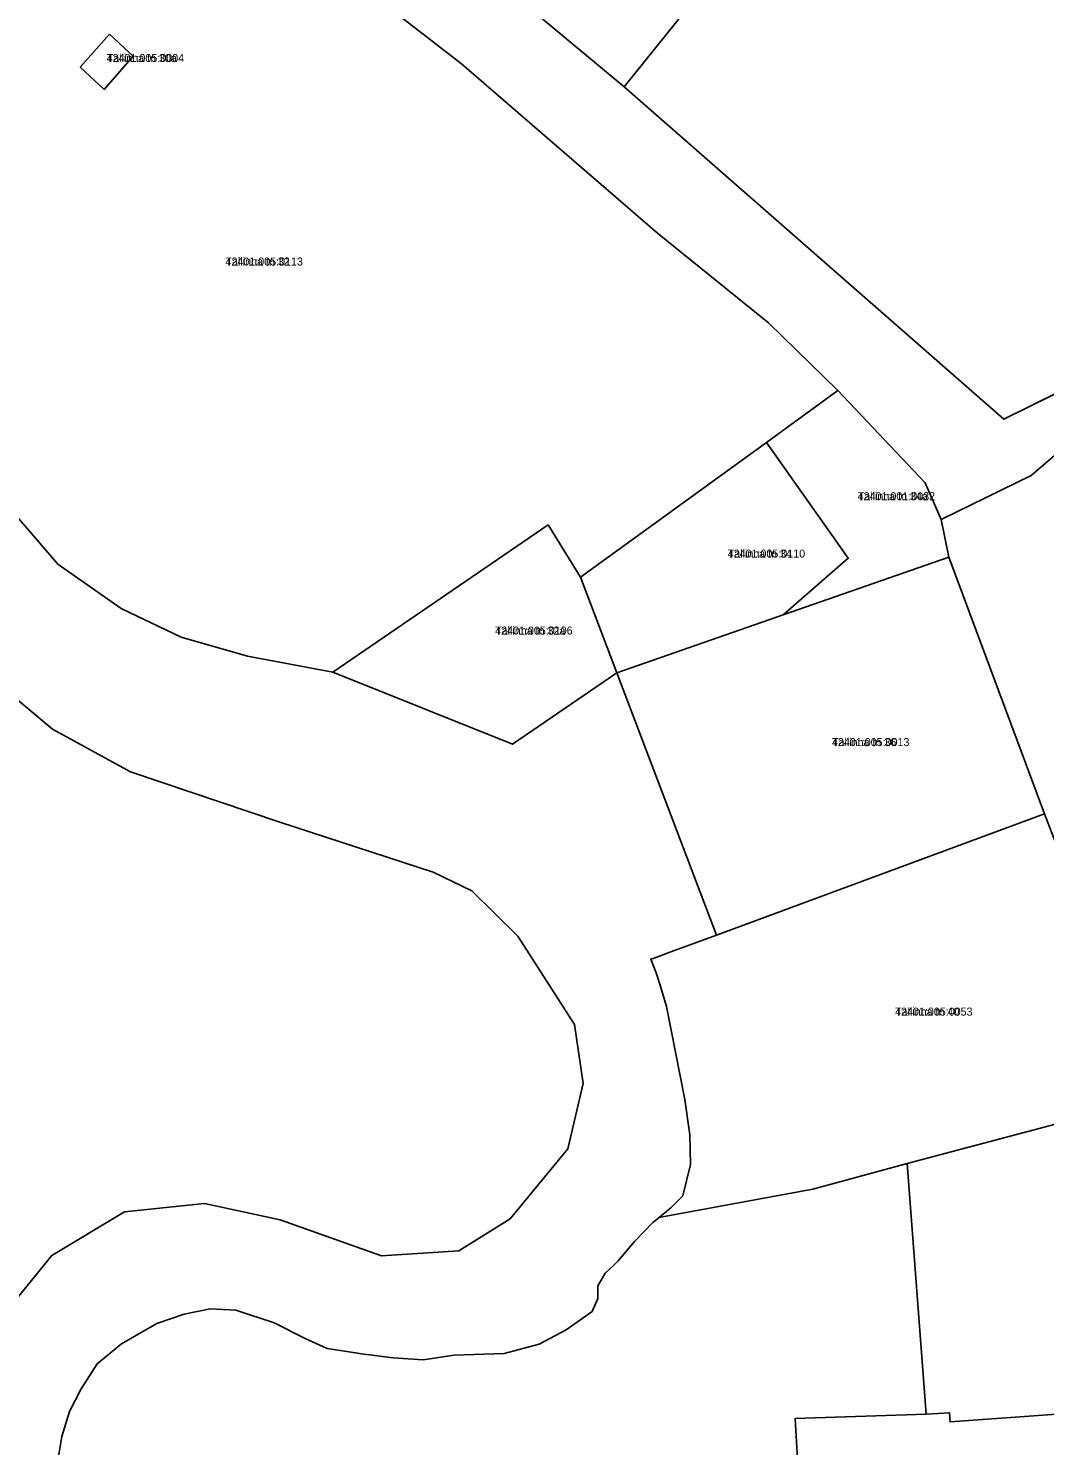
# Model space of a CAD drawing. Extents: x 595979 to 597983, y 6604231 to 6607350.
# Drawn here: x 597254.4 to 597444.7, y 6605784.1 to 6606049.7 of the extents above; entities that cross this region are included whole.
import ezdxf

# ---------------------------------------------------------------- set-up
doc = ezdxf.new("R2010")
doc.units = 0
for name, color, linetype in [('L_AADRESS', 7, 'Continuous'), ('PIIR', 7, 'Continuous'), ('TUNNUS', 7, 'Continuous')]:
    doc.layers.add(name, color=color, linetype=linetype)

msp = doc.modelspace()

# ---------------------------------------------------------------- linework, layer by layer
at = {"layer": 'PIIR'}
for points in [[(597442.87, 6606212.74), (597489.89, 6606169.48), (597453.56, 6606148.67), (597452.77, 6606147.89), (597450.68, 6606145.57), (597451.19, 6606145.11), (597448.87, 6606142.54), (597445.63, 6606138.93), (597446.17, 6606138.41), (597365.99, 6606038.68), (597323.41, 6606074.19)], [(597452.77, 6606147.89), (597453.56, 6606148.67), (597503.14, 6606104.38), (597508.49, 6606106.92), (597528.5, 6606116.72), (597541.59, 6606123.09), (597550.67, 6606127.51), (597561.12, 6606105.01), (597587.91, 6606081.73), (597565.06, 6606039.67), (597437.08, 6605976.43), (597365.99, 6606038.68), (597446.17, 6606138.41), (597445.63, 6606138.93), (597448.87, 6606142.54), (597451.19, 6606145.11), (597450.68, 6606145.57)], [(597269.6, 6606048.59), (597274, 6606044.43), (597268.58, 6606038.16), (597264.11, 6606042.35)], [(597269.6, 6606048.59), (597264.11, 6606042.35), (597268.58, 6606038.16), (597274, 6606044.43)], [(597426.77, 6605950.57), (597395.75, 6605939.78), (597407.95, 6605950.35), (597392.63, 6605972.06), (597405.98, 6605981.76), (597422.33, 6605964.47), (597425.35, 6605957.62)], [(597425.35, 6605957.62), (597442.2, 6605965.89), (597453.99, 6605975.96), (597470.29, 6605942.41), (597457.03, 6605934.28), (597464.18, 6605921.48), (597470.45, 6605908.95), (597473.75, 6605900.95), (597476.41, 6605894.47), (597488.98, 6605855.16), (597465.11, 6605849.2), (597444.67, 6605902.49), (597426.77, 6605950.57)], [(597407.95, 6605950.35), (597395.75, 6605939.78), (597364.62, 6605928.9), (597357.8, 6605946.81), (597392.63, 6605972.06)], [(597311.39, 6605928.99), (597351.75, 6605956.6), (597357.8, 6605946.81), (597364.62, 6605928.9), (597345.04, 6605915.51)], [(597426.77, 6605950.57), (597444.67, 6605902.49), (597383.26, 6605879.75), (597364.62, 6605928.9), (597395.75, 6605939.78)], [(597383.26, 6605879.75), (597444.67, 6605902.49), (597465.11, 6605849.2), (597418.98, 6605836.92), (597401.29, 6605832.16), (597373.83, 6605827.07), (597372.52, 6605826.83), (597374.74, 6605828.62), (597376.34, 6605830.27), (597376.96, 6605830.91), (597378.4, 6605836.79), (597378.28, 6605842.33), (597377.33, 6605848.93), (597373.91, 6605866.35), (597372.63, 6605870.56), (597371.98, 6605872.7), (597370.94, 6605875.21), (597371.57, 6605875.45), (597374.73, 6605876.61)], [(597426.92, 6605790.23), (597422.51, 6605790), (597418.98, 6605836.92), (597465.11, 6605849.2), (597470.46, 6605791.65), (597427.02, 6605788.53)], [(597422.51, 6605790), (597426.92, 6605790.23), (597427.02, 6605788.53), (597470.46, 6605791.65), (597472.15, 6605763.69), (597423.76, 6605750.56), (597400.63, 6605743.31), (597398.02, 6605789.18)]]:
    msp.add_lwpolyline(points, close=True, dxfattribs=at)
for points in [[(597280.71, 6606085.45), (597335.48, 6606042.99), (597372.22, 6606011.27), (597392.99, 6605994.46), (597405.98, 6605981.76), (597392.63, 6605972.06), (597357.8, 6605946.81), (597351.75, 6605956.6), (597311.39, 6605928.99), (597295.41, 6605931.99), (597283.03, 6605935.59), (597271.76, 6605940.97), (597259.9, 6605949.24), (597248.42, 6605962.57)], [(597323.41, 6606074.19), (597365.99, 6606038.68), (597437.08, 6605976.43), (597450.63, 6605983.12), (597453.99, 6605975.96), (597442.2, 6605965.89), (597425.35, 6605957.62), (597422.33, 6605964.47), (597405.98, 6605981.76), (597392.99, 6605994.46), (597372.22, 6606011.27), (597335.48, 6606042.99), (597280.71, 6606085.45)], [(597248.42, 6605962.57), (597259.9, 6605949.24), (597271.76, 6605940.97), (597283.03, 6605935.59), (597295.41, 6605931.99), (597311.39, 6605928.99), (597345.04, 6605915.51), (597364.62, 6605928.9), (597383.26, 6605879.75), (597374.73, 6605876.61), (597371.57, 6605875.45), (597370.94, 6605875.21), (597371.98, 6605872.7), (597372.63, 6605870.56), (597373.91, 6605866.35), (597377.33, 6605848.93), (597378.28, 6605842.33), (597378.4, 6605836.79), (597376.96, 6605830.91), (597376.34, 6605830.27), (597374.74, 6605828.62), (597372.52, 6605826.83), (597371.36, 6605825.9), (597367.91, 6605822.32), (597364.87, 6605818.69), (597363.88, 6605817.76), (597362.44, 6605816.42), (597361.82, 6605815.39), (597361.03, 6605814.05), (597361.02, 6605811.64), (597359.98, 6605809.23), (597355.11, 6605805.76), (597350.05, 6605803.09), (597343.49, 6605801.34), (597334.12, 6605801.05), (597328.35, 6605800.19), (597322.71, 6605800.54), (597316.78, 6605801.31), (597315.64, 6605801.46), (597310.32, 6605802.28), (597306.24, 6605804.16), (597300.4, 6605807.08), (597293.23, 6605809.47), (597288.41, 6605809.72), (597283.55, 6605808.69), (597278.47, 6605806.99), (597271.81, 6605803.13), (597267.27, 6605799.4), (597264.3, 6605794.73), (597262.06, 6605790.48), (597260.68, 6605785.82), (597259.93, 6605781.32)], [(597245.66, 6605929.36), (597258.88, 6605918.33), (597273.5, 6605910.36), (597301.49, 6605900.93), (597330.22, 6605891.55), (597337.46, 6605888.05), (597346.05, 6605879.57), (597356.66, 6605863.02), (597358.32, 6605851.96), (597355.39, 6605839.72), (597344.65, 6605826.61), (597335, 6605820.61), (597320.5, 6605819.65), (597301.57, 6605826.37), (597287.38, 6605829.47), (597272.4, 6605827.87), (597258.81, 6605819.74), (597248.39, 6605807)], [(597248.39, 6605807), (597258.81, 6605819.74), (597272.4, 6605827.87), (597287.38, 6605829.47), (597301.57, 6605826.37), (597320.5, 6605819.65), (597335, 6605820.61), (597344.65, 6605826.61), (597355.39, 6605839.72), (597358.32, 6605851.96), (597356.66, 6605863.02), (597346.05, 6605879.57), (597337.46, 6605888.05), (597330.22, 6605891.55), (597301.49, 6605900.93), (597273.5, 6605910.36), (597258.88, 6605918.33), (597245.66, 6605929.36)], [(597259.93, 6605781.32), (597260.68, 6605785.82), (597262.06, 6605790.48), (597264.3, 6605794.73), (597267.27, 6605799.4), (597271.81, 6605803.13), (597278.47, 6605806.99), (597283.55, 6605808.69), (597288.41, 6605809.72), (597293.23, 6605809.47), (597300.4, 6605807.08), (597306.24, 6605804.16), (597310.32, 6605802.28), (597315.64, 6605801.46), (597316.78, 6605801.31), (597322.71, 6605800.54), (597328.35, 6605800.19), (597334.12, 6605801.05), (597343.49, 6605801.34), (597350.05, 6605803.09), (597355.11, 6605805.76), (597359.98, 6605809.23), (597361.02, 6605811.64), (597361.03, 6605814.05), (597361.82, 6605815.39), (597362.44, 6605816.42), (597363.88, 6605817.76), (597364.87, 6605818.69), (597367.91, 6605822.32), (597371.36, 6605825.9), (597372.52, 6605826.83), (597373.83, 6605827.07), (597401.29, 6605832.16), (597418.98, 6605836.92), (597422.51, 6605790), (597398.02, 6605789.18), (597400.63, 6605743.31)]]:
    msp.add_lwpolyline(points, dxfattribs=at)

# ---------------------------------------------------------------- texts
at = {"layer": 'L_AADRESS'}
for s, p in [('Tallinna tn 30a', (597269.05, 6606043.34)), ('Tallinna tn 32', (597291.3, 6606005.21)), ('Tallinna tn 34a', (597409.7, 6605961.23)), ('Tallinna tn 34', (597385.36, 6605950.48)), ('Tallinna tn 32a', (597341.81, 6605936.06)), ('Tallinna tn 36', (597404.89, 6605915.16)), ('Tallinna tn 40', (597416.71, 6605864.66))]:
    msp.add_text(s, height=1.5, dxfattribs=at).set_placement(p)
at = {"layer": 'TUNNUS'}
for s, p in [('42401:005:0004', (597269.05, 6606043.34)), ('42401:005:0113', (597291.3, 6606005.21)), ('42401:001:0032', (597409.7, 6605961.23)), ('42401:005:0110', (597385.36, 6605950.48)), ('42401:005:0106', (597341.81, 6605936.06)), ('42401:005:0013', (597404.89, 6605915.16)), ('42401:005:0053', (597416.71, 6605864.66))]:
    msp.add_text(s, height=1.5, dxfattribs=at).set_placement(p)

doc.saveas('drawing.dxf')
